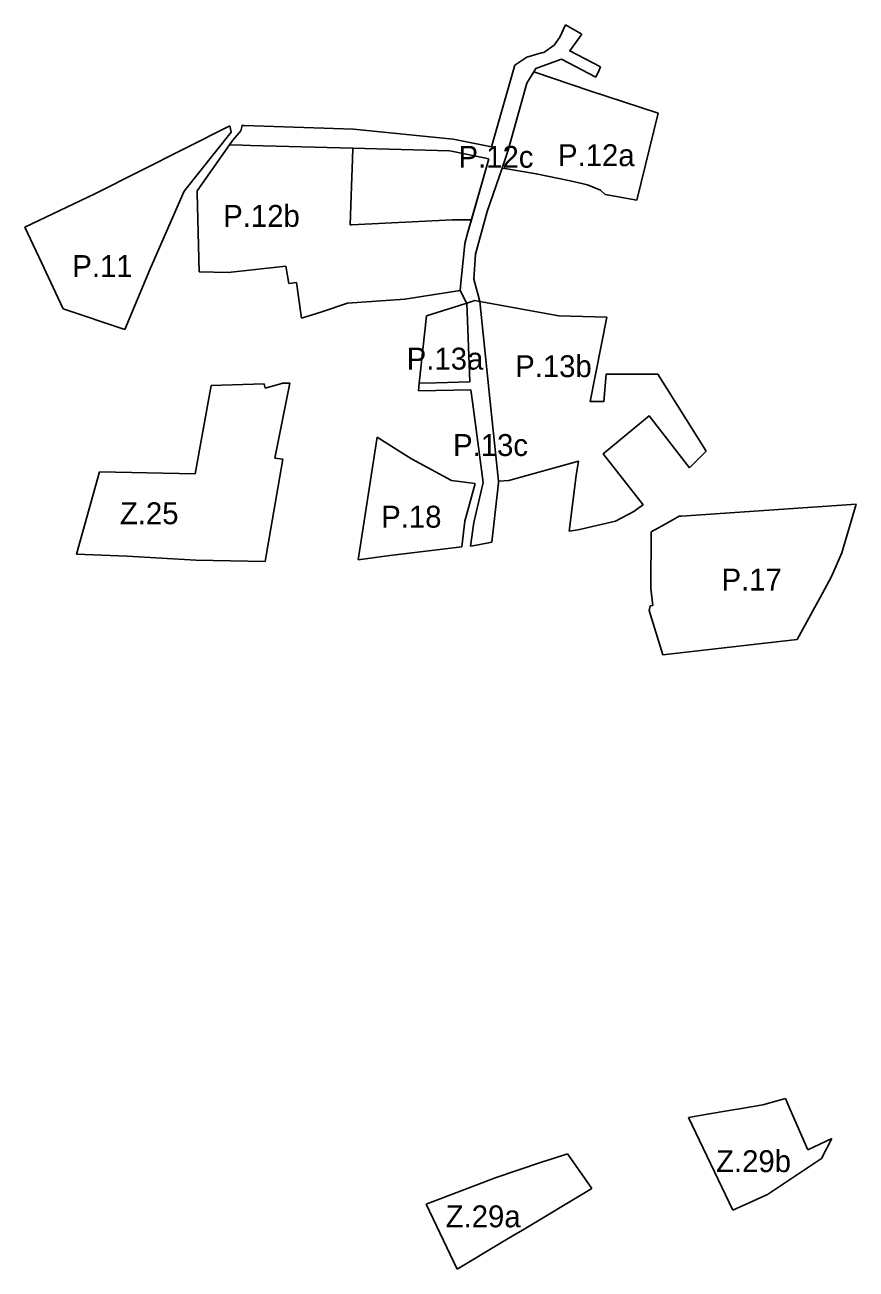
# Model space of a CAD drawing. Extents: x -438701 to -435614, y -1126017 to -1121766.
# Drawn here: x -438657 to -438278, y -1124714 to -1124146 of the extents above; entities that cross this region are included whole.
import ezdxf

# ---------------------------------------------------------------- set-up
doc = ezdxf.new("R2010")
doc.units = 0
for name, color, linetype in [('NAVRH', 7, 'Continuous'), ('STAV', 7, 'Continuous'), ('Vrstva 3', 7, 'Continuous'), ('Vrstva 6', 7, 'Continuous'), ('Vrstva 7', 7, 'Continuous'), ('Vrstva 9', 7, 'Continuous')]:
    doc.layers.add(name, color=color, linetype=linetype)

msp = doc.modelspace()

# ---------------------------------------------------------------- linework, layer by layer
at = {"layer": 'NAVRH'}
for p, q in [((-438572.39, -1124310.34), (-438579.69, -1124350.66)), ((-438548.15, -1124309.59), (-438572.39, -1124310.34)), ((-438547.64, -1124311.5), (-438548.15, -1124309.59)), ((-438540.13, -1124309.49), (-438547.64, -1124311.5)), ((-438543.36, -1124343.46), (-438536.39, -1124309.23)), ((-438536.39, -1124309.23), (-438540.17, -1124309.35)), ((-438540.17, -1124309.35), (-438540.13, -1124309.49)), ((-438579.69, -1124350.66), (-438623.38, -1124349.81)), ((-438610.69, -1124388.29), (-438579.35, -1124390.02)), ((-438579.35, -1124390.02), (-438547.72, -1124390.62)), ((-438547.72, -1124390.62), (-438547.25, -1124387.88)), ((-438310.12, -1124635.86), (-438320.49, -1124638.7)), ((-438309.13, -1124638.43), (-438310.12, -1124635.86)), ((-438299.98, -1124659.22), (-438309.13, -1124638.43)), ((-438346.75, -1124643.14), (-438354.53, -1124644.46)), ((-438354.53, -1124644.46), (-438334.17, -1124686.69)), ((-438289.07, -1124654.07), (-438299.98, -1124659.22)), ((-438293.79, -1124663.17), (-438289.07, -1124654.07)), ((-438318.45, -1124679.6), (-438293.79, -1124663.17)), ((-438421.5, -1124664.88), (-438442.23, -1124671.92)), ((-438442.23, -1124671.92), (-438474.16, -1124684.08)), ((-438398.6, -1124676.83), (-438398.85, -1124676.47)), ((-438334.17, -1124686.69), (-438318.45, -1124679.6)), ((-438474.16, -1124684.08), (-438460.03, -1124713.66))]:
    msp.add_line(p, q, dxfattribs=at)
for points in [[(-438547.25, -1124387.88), (-438539.7, -1124343.99), (-438543.36, -1124343.46)], [(-438623.38, -1124349.81), (-438633.77, -1124387.29), (-438610.69, -1124388.29)], [(-438320.49, -1124638.7), (-438330.3, -1124640.36), (-438334.93, -1124641.14), (-438346.75, -1124643.14)], [(-438409.64, -1124661.08), (-438416.72, -1124663.25), (-438421.5, -1124664.88)], [(-438398.85, -1124676.47), (-438408.93, -1124662.09), (-438409.64, -1124661.08)], [(-438460.03, -1124713.66), (-438438.34, -1124700.66), (-438433.47, -1124697.74), (-438431.04, -1124696.28), (-438398.6, -1124676.83)]]:
    msp.add_lwpolyline(points, dxfattribs=at)
at = {"layer": 'Vrstva 3'}
for p, q in [((-438410.68, -1124145.76), (-438413.25, -1124151.3)), ((-438403.24, -1124150), (-438410.68, -1124145.76)), ((-438407.85, -1124156.48), (-438403.24, -1124150)), ((-438416.19, -1124162.82), (-438412.51, -1124161.48)), ((-438412.51, -1124161.48), (-438396.78, -1124169.65)), ((-438433.82, -1124164.13), (-438444.44, -1124201.43)), ((-438425.04, -1124167.12), (-438428.21, -1124172.3)), ((-438428.21, -1124172.3), (-438425.04, -1124167.12)), ((-438399.58, -1124175.81), (-438425.04, -1124167.12)), ((-438428.21, -1124172.3), (-438436.78, -1124203)), ((-438436.78, -1124203), (-438428.21, -1124172.3)), ((-438368.37, -1124186.12), (-438399.58, -1124175.81)), ((-438378.08, -1124225.73), (-438368.37, -1124186.12)), ((-438563.77, -1124191.78), (-438625.53, -1124222.8)), ((-438563.18, -1124194.73), (-438563.77, -1124191.78)), ((-438584.64, -1124221.61), (-438563.18, -1124194.73)), ((-438558.89, -1124194.14), (-438562.44, -1124198.37)), ((-438461.91, -1124197.85), (-438507.43, -1124193.38)), ((-438563.95, -1124200.51), (-438578.71, -1124221.44)), ((-438562.44, -1124198.37), (-438563.95, -1124200.51)), ((-438558.18, -1124200.66), (-438563.95, -1124200.51)), ((-438563.95, -1124200.51), (-438558.18, -1124200.66)), ((-438554.42, -1124200.77), (-438558.18, -1124200.66)), ((-438558.18, -1124200.66), (-438554.42, -1124200.77)), ((-438507.72, -1124202.05), (-438554.42, -1124200.77)), ((-438554.42, -1124200.77), (-438507.72, -1124202.05)), ((-438507.88, -1124207.04), (-438507.72, -1124202.05)), ((-438507.72, -1124202.05), (-438463.62, -1124203.26)), ((-438463.62, -1124203.26), (-438461.94, -1124203.6)), ((-438444.44, -1124201.43), (-438461.91, -1124197.85)), ((-438436.78, -1124203), (-438439.6, -1124211.18)), ((-438439.6, -1124211.18), (-438436.78, -1124203)), ((-438508.29, -1124219.38), (-438507.88, -1124207.04)), ((-438461.94, -1124203.6), (-438445.6, -1124206.87)), ((-438445.6, -1124206.87), (-438455.16, -1124240.33)), ((-438446.4, -1124230.87), (-438439.6, -1124211.18)), ((-438508.87, -1124237.03), (-438508.29, -1124219.38)), ((-438625.53, -1124222.8), (-438657.4, -1124238.13)), ((-438600.25, -1124257.14), (-438584.64, -1124221.61)), ((-438578.71, -1124221.44), (-438578.71, -1124222.39)), ((-438578.71, -1124222.39), (-438577.81, -1124258.4)), ((-438392.51, -1124223.25), (-438378.08, -1124225.73)), ((-438451.69, -1124250.43), (-438446.4, -1124230.87)), ((-438453.54, -1124234.67), (-438462.13, -1124234.67)), ((-438455.16, -1124240.33), (-438453.54, -1124234.67)), ((-438657.4, -1124238.13), (-438649.87, -1124254.19)), ((-438456.63, -1124245.47), (-438455.16, -1124240.33)), ((-438455.16, -1124240.33), (-438456.63, -1124245.47)), ((-438458.38, -1124263.51), (-438456.95, -1124248.74)), ((-438456.95, -1124248.74), (-438458.38, -1124263.51)), ((-438456.95, -1124248.74), (-438456.63, -1124245.47)), ((-438456.63, -1124245.47), (-438456.95, -1124248.74)), ((-438452.46, -1124261.79), (-438451.69, -1124250.43)), ((-438611.81, -1124284.81), (-438600.25, -1124257.14)), ((-438577.81, -1124258.4), (-438564.55, -1124258.84)), ((-438564.55, -1124258.84), (-438553.52, -1124257.58)), ((-438553.52, -1124257.58), (-438538.33, -1124255.84)), ((-438538.33, -1124255.84), (-438536.95, -1124263.85)), ((-438536.95, -1124263.85), (-438533.42, -1124263.35)), ((-438533.42, -1124263.35), (-438531.11, -1124279.55)), ((-438458.72, -1124266.98), (-438458.38, -1124263.51)), ((-438458.38, -1124263.51), (-438458.72, -1124266.98)), ((-438451.33, -1124265.82), (-438452.46, -1124261.79)), ((-438450.59, -1124268.57), (-438451.33, -1124265.82)), ((-438458.72, -1124266.98), (-438456.07, -1124272.01)), ((-438455.7, -1124272.72), (-438451.99, -1124271.53)), ((-438451.99, -1124271.53), (-438455.7, -1124272.72)), ((-438451.99, -1124271.53), (-438449.67, -1124271.95)), ((-438449.67, -1124271.95), (-438451.99, -1124271.53)), ((-438449.67, -1124271.95), (-438450.59, -1124268.57)), ((-438639.93, -1124275.4), (-438611.81, -1124284.81)), ((-438461.91, -1124274.71), (-438474.13, -1124278.62)), ((-438455.7, -1124272.72), (-438461.91, -1124274.71)), ((-438456.07, -1124272.01), (-438455.93, -1124272.29)), ((-438455.93, -1124272.29), (-438455.7, -1124272.72)), ((-438454.27, -1124308.74), (-438455.7, -1124272.72)), ((-438455.7, -1124272.72), (-438454.27, -1124308.74)), ((-438449.67, -1124271.95), (-438444.96, -1124317.8)), ((-438444.96, -1124317.8), (-438449.67, -1124271.95)), ((-438474.13, -1124278.62), (-438477.39, -1124309.23)), ((-438346.45, -1124340.28), (-438368.49, -1124305.17)), ((-438477.39, -1124309.23), (-438477.78, -1124312.76)), ((-438477.39, -1124309.23), (-438469.62, -1124309.07)), ((-438469.62, -1124309.07), (-438477.39, -1124309.23)), ((-438469.62, -1124309.07), (-438454.27, -1124308.74)), ((-438454.27, -1124308.74), (-438469.62, -1124309.07)), ((-438477.78, -1124312.76), (-438453.79, -1124312.36)), ((-438453.79, -1124312.36), (-438453.06, -1124317.81)), ((-438453.06, -1124317.81), (-438448.16, -1124354.7)), ((-438444.96, -1124317.8), (-438441.24, -1124354.09)), ((-438441.24, -1124354.09), (-438444.96, -1124317.8)), ((-438444.96, -1124317.8), (-438444.96, -1124317.8)), ((-438444.96, -1124317.8), (-438444.96, -1124317.8)), ((-438496.56, -1124333.94), (-438505.21, -1124389.9)), ((-438486.97, -1124340.05), (-438496.56, -1124333.94)), ((-438480.86, -1124343.8), (-438486.97, -1124340.05)), ((-438462.72, -1124353.76), (-438480.86, -1124343.8)), ((-438354.09, -1124347.9), (-438346.45, -1124340.28)), ((-438451.84, -1124355.13), (-438462.72, -1124353.76)), ((-438456.53, -1124372.33), (-438451.84, -1124355.13)), ((-438448.16, -1124354.7), (-438452.48, -1124372.83)), ((-438277.96, -1124364.45), (-438357.71, -1124369.98)), ((-438284.52, -1124386.69), (-438277.96, -1124364.45)), ((-438457.93, -1124384), (-438456.53, -1124372.33)), ((-438452.48, -1124372.83), (-438454.01, -1124383.75)), ((-438363.73, -1124372.82), (-438371.47, -1124377.17)), ((-438358.81, -1124370.06), (-438363.73, -1124372.82)), ((-438357.71, -1124369.98), (-438358.81, -1124370.06)), ((-438408.88, -1124376.91), (-438404.82, -1124376.23)), ((-438371.47, -1124377.17), (-438371.73, -1124403.04)), ((-438490.87, -1124387.9), (-438457.93, -1124384)), ((-438454.01, -1124383.75), (-438451.27, -1124383.23)), ((-438451.27, -1124383.23), (-438444.23, -1124381.88)), ((-438505.21, -1124389.9), (-438490.87, -1124387.9)), ((-438289.23, -1124397.56), (-438284.52, -1124386.69)), ((-438293.49, -1124405.39), (-438289.23, -1124397.56)), ((-438371.73, -1124403.04), (-438370.76, -1124410.77)), ((-438304.86, -1124426.28), (-438293.49, -1124405.39)), ((-438371.91, -1124410.92), (-438372.46, -1124413.12)), ((-438372.46, -1124413.12), (-438366.13, -1124433.36)), ((-438370.76, -1124410.77), (-438371.91, -1124410.92)), ((-438366.13, -1124433.36), (-438324.89, -1124428.6)), ((-438324.89, -1124428.6), (-438304.86, -1124426.28))]:
    msp.add_line(p, q, dxfattribs=at)
for points in [[(-438413.25, -1124151.3), (-438415.8, -1124155.01), (-438420.57, -1124158.3)], [(-438394.63, -1124164.9), (-438408.69, -1124157.66), (-438407.85, -1124156.48)], [(-438420.57, -1124158.3), (-438421.6, -1124158.59), (-438428.21, -1124160.42), (-438433.82, -1124164.13)], [(-438425.04, -1124167.12), (-438424.18, -1124165.72), (-438416.19, -1124162.82)], [(-438396.78, -1124169.65), (-438395.43, -1124166.67), (-438394.63, -1124164.9)], [(-438507.43, -1124193.38), (-438557.27, -1124191.7), (-438558.27, -1124191.67), (-438558.89, -1124194.14)], [(-438439.6, -1124211.18), (-438438.29, -1124211.37), (-438424, -1124213.73), (-438408.51, -1124217.01), (-438400.53, -1124218.7), (-438394.57, -1124221.19), (-438392.51, -1124223.25)], [(-438462.13, -1124234.67), (-438508.26, -1124237), (-438508.87, -1124237.03)], [(-438649.87, -1124254.19), (-438644.51, -1124265.63), (-438639.93, -1124275.4)], [(-438531.11, -1124279.55), (-438522.35, -1124276.86), (-438510.06, -1124272.84), (-438484.02, -1124270.93), (-438458.72, -1124266.98)], [(-438391.78, -1124279.14), (-438413.63, -1124278.54), (-438449.67, -1124271.95)], [(-438368.49, -1124305.17), (-438392.08, -1124305.24), (-438393.17, -1124317.69), (-438399.29, -1124317.72), (-438391.78, -1124279.14)], [(-438375.22, -1124364.76), (-438393.49, -1124341.6), (-438372.43, -1124324.16), (-438354.09, -1124347.9)], [(-438441.24, -1124354.09), (-438436.45, -1124353.73), (-438404.63, -1124344.93), (-438405.74, -1124351.49), (-438408.88, -1124376.91)], [(-438444.23, -1124381.88), (-438441.17, -1124354.72), (-438441.24, -1124354.09)], [(-438404.82, -1124376.23), (-438387.84, -1124372.24), (-438379.48, -1124367.79), (-438377.56, -1124366.43), (-438375.22, -1124364.76)]]:
    msp.add_lwpolyline(points, dxfattribs=at)
at = {"layer": 'Vrstva 6'}
for p, q in [((-438572.39, -1124310.34), (-438579.69, -1124350.66)), ((-438548.15, -1124309.59), (-438572.39, -1124310.34)), ((-438547.64, -1124311.5), (-438548.15, -1124309.59)), ((-438540.13, -1124309.49), (-438547.64, -1124311.5)), ((-438543.36, -1124343.46), (-438536.39, -1124309.23)), ((-438536.39, -1124309.23), (-438540.17, -1124309.35)), ((-438540.17, -1124309.35), (-438540.13, -1124309.49)), ((-438579.69, -1124350.66), (-438623.38, -1124349.81)), ((-438610.69, -1124388.29), (-438579.35, -1124390.02)), ((-438579.35, -1124390.02), (-438547.72, -1124390.62)), ((-438547.72, -1124390.62), (-438547.25, -1124387.88)), ((-438310.12, -1124635.86), (-438320.49, -1124638.7)), ((-438309.13, -1124638.43), (-438310.12, -1124635.86)), ((-438299.98, -1124659.22), (-438309.13, -1124638.43)), ((-438346.75, -1124643.14), (-438354.53, -1124644.46)), ((-438354.53, -1124644.46), (-438334.17, -1124686.69)), ((-438289.07, -1124654.07), (-438299.98, -1124659.22)), ((-438293.79, -1124663.17), (-438289.07, -1124654.07)), ((-438318.45, -1124679.6), (-438293.79, -1124663.17)), ((-438421.5, -1124664.88), (-438442.23, -1124671.92)), ((-438442.23, -1124671.92), (-438474.16, -1124684.08)), ((-438398.6, -1124676.83), (-438398.85, -1124676.47)), ((-438334.17, -1124686.69), (-438318.45, -1124679.6)), ((-438474.16, -1124684.08), (-438460.03, -1124713.66))]:
    msp.add_line(p, q, dxfattribs=at)
for points in [[(-438547.25, -1124387.88), (-438539.7, -1124343.99), (-438543.36, -1124343.46)], [(-438623.38, -1124349.81), (-438633.77, -1124387.29), (-438610.69, -1124388.29)], [(-438320.49, -1124638.7), (-438330.3, -1124640.36), (-438334.93, -1124641.14), (-438346.75, -1124643.14)], [(-438409.64, -1124661.08), (-438416.72, -1124663.25), (-438421.5, -1124664.88)], [(-438398.85, -1124676.47), (-438408.93, -1124662.09), (-438409.64, -1124661.08)], [(-438460.03, -1124713.66), (-438438.34, -1124700.66), (-438433.47, -1124697.74), (-438431.04, -1124696.28), (-438398.6, -1124676.83)]]:
    msp.add_lwpolyline(points, dxfattribs=at)
at = {"layer": 'Vrstva 7'}
for p, q in [((-438410.68, -1124145.76), (-438413.25, -1124151.3)), ((-438403.24, -1124150), (-438410.68, -1124145.76)), ((-438407.85, -1124156.48), (-438403.24, -1124150)), ((-438416.19, -1124162.82), (-438412.51, -1124161.48)), ((-438412.51, -1124161.48), (-438396.78, -1124169.65)), ((-438433.82, -1124164.13), (-438444.44, -1124201.43)), ((-438425.04, -1124167.12), (-438428.21, -1124172.3)), ((-438428.21, -1124172.3), (-438425.04, -1124167.12)), ((-438399.58, -1124175.81), (-438425.04, -1124167.12)), ((-438428.21, -1124172.3), (-438436.78, -1124203)), ((-438436.78, -1124203), (-438428.21, -1124172.3)), ((-438368.37, -1124186.12), (-438399.58, -1124175.81)), ((-438378.08, -1124225.73), (-438368.37, -1124186.12)), ((-438563.77, -1124191.78), (-438625.53, -1124222.8)), ((-438563.18, -1124194.73), (-438563.77, -1124191.78)), ((-438584.64, -1124221.61), (-438563.18, -1124194.73)), ((-438558.89, -1124194.14), (-438562.44, -1124198.37)), ((-438461.91, -1124197.85), (-438507.43, -1124193.38)), ((-438563.95, -1124200.51), (-438578.71, -1124221.44)), ((-438562.44, -1124198.37), (-438563.95, -1124200.51)), ((-438558.18, -1124200.66), (-438563.95, -1124200.51)), ((-438563.95, -1124200.51), (-438558.18, -1124200.66)), ((-438554.42, -1124200.77), (-438558.18, -1124200.66)), ((-438558.18, -1124200.66), (-438554.42, -1124200.77)), ((-438507.72, -1124202.05), (-438554.42, -1124200.77)), ((-438554.42, -1124200.77), (-438507.72, -1124202.05)), ((-438507.88, -1124207.04), (-438507.72, -1124202.05)), ((-438507.72, -1124202.05), (-438463.62, -1124203.26)), ((-438463.62, -1124203.26), (-438461.94, -1124203.6)), ((-438444.44, -1124201.43), (-438461.91, -1124197.85)), ((-438436.78, -1124203), (-438439.6, -1124211.18)), ((-438439.6, -1124211.18), (-438436.78, -1124203)), ((-438508.29, -1124219.38), (-438507.88, -1124207.04)), ((-438461.94, -1124203.6), (-438445.6, -1124206.87)), ((-438445.6, -1124206.87), (-438453.54, -1124234.67)), ((-438446.4, -1124230.87), (-438439.6, -1124211.18)), ((-438508.87, -1124237.03), (-438508.29, -1124219.38)), ((-438625.53, -1124222.8), (-438657.4, -1124238.13)), ((-438600.25, -1124257.14), (-438584.64, -1124221.61)), ((-438578.71, -1124221.44), (-438578.71, -1124222.39)), ((-438578.71, -1124222.39), (-438577.81, -1124258.4)), ((-438392.51, -1124223.25), (-438378.08, -1124225.73)), ((-438451.69, -1124250.43), (-438446.4, -1124230.87)), ((-438453.54, -1124234.67), (-438462.13, -1124234.67)), ((-438455.16, -1124240.33), (-438453.54, -1124234.67)), ((-438453.54, -1124234.67), (-438455.16, -1124240.33)), ((-438657.4, -1124238.13), (-438649.87, -1124254.19)), ((-438456.63, -1124245.47), (-438455.16, -1124240.33)), ((-438455.16, -1124240.33), (-438456.63, -1124245.47)), ((-438458.38, -1124263.51), (-438456.95, -1124248.74)), ((-438456.95, -1124248.74), (-438458.38, -1124263.51)), ((-438456.95, -1124248.74), (-438456.63, -1124245.47)), ((-438456.63, -1124245.47), (-438456.95, -1124248.74)), ((-438452.46, -1124261.79), (-438451.69, -1124250.43)), ((-438611.81, -1124284.81), (-438600.25, -1124257.14)), ((-438577.81, -1124258.4), (-438564.55, -1124258.84)), ((-438564.55, -1124258.84), (-438553.52, -1124257.58)), ((-438553.52, -1124257.58), (-438538.33, -1124255.84)), ((-438538.33, -1124255.84), (-438536.95, -1124263.85)), ((-438536.95, -1124263.85), (-438533.42, -1124263.35)), ((-438533.42, -1124263.35), (-438531.11, -1124279.55)), ((-438458.72, -1124266.98), (-438458.38, -1124263.51)), ((-438458.38, -1124263.51), (-438458.72, -1124266.98)), ((-438451.33, -1124265.82), (-438452.46, -1124261.79)), ((-438450.59, -1124268.57), (-438451.33, -1124265.82)), ((-438458.72, -1124266.98), (-438456.07, -1124272.01)), ((-438455.7, -1124272.72), (-438451.99, -1124271.53)), ((-438451.99, -1124271.53), (-438455.7, -1124272.72)), ((-438451.99, -1124271.53), (-438449.67, -1124271.95)), ((-438449.67, -1124271.95), (-438451.99, -1124271.53)), ((-438449.67, -1124271.95), (-438450.59, -1124268.57)), ((-438639.93, -1124275.4), (-438611.81, -1124284.81)), ((-438461.91, -1124274.71), (-438474.13, -1124278.62)), ((-438455.7, -1124272.72), (-438461.91, -1124274.71)), ((-438456.07, -1124272.01), (-438455.93, -1124272.29)), ((-438455.93, -1124272.29), (-438455.7, -1124272.72)), ((-438455.7, -1124272.72), (-438454.27, -1124308.74)), ((-438454.27, -1124308.74), (-438455.7, -1124272.72)), ((-438449.67, -1124271.95), (-438444.96, -1124317.8)), ((-438444.96, -1124317.8), (-438449.67, -1124271.95)), ((-438474.13, -1124278.62), (-438477.39, -1124309.23)), ((-438346.45, -1124340.28), (-438368.49, -1124305.17)), ((-438477.39, -1124309.23), (-438477.78, -1124312.76)), ((-438469.62, -1124309.07), (-438477.39, -1124309.23)), ((-438477.39, -1124309.23), (-438469.62, -1124309.07)), ((-438454.27, -1124308.74), (-438469.62, -1124309.07)), ((-438469.62, -1124309.07), (-438454.27, -1124308.74)), ((-438477.78, -1124312.76), (-438453.79, -1124312.36)), ((-438453.79, -1124312.36), (-438453.06, -1124317.81)), ((-438453.06, -1124317.81), (-438448.16, -1124354.7)), ((-438444.96, -1124317.8), (-438441.24, -1124354.09)), ((-438441.24, -1124354.09), (-438444.96, -1124317.8)), ((-438496.56, -1124333.94), (-438505.21, -1124389.9)), ((-438486.97, -1124340.05), (-438496.56, -1124333.94)), ((-438480.86, -1124343.8), (-438486.97, -1124340.05)), ((-438462.72, -1124353.76), (-438480.86, -1124343.8)), ((-438354.09, -1124347.9), (-438346.45, -1124340.28)), ((-438451.84, -1124355.13), (-438462.72, -1124353.76)), ((-438456.53, -1124372.33), (-438451.84, -1124355.13)), ((-438448.16, -1124354.7), (-438452.48, -1124372.83)), ((-438277.96, -1124364.45), (-438357.71, -1124369.98)), ((-438284.52, -1124386.69), (-438277.96, -1124364.45)), ((-438457.93, -1124384), (-438456.53, -1124372.33)), ((-438452.48, -1124372.83), (-438454.01, -1124383.75)), ((-438363.73, -1124372.82), (-438371.47, -1124377.17)), ((-438358.81, -1124370.06), (-438363.73, -1124372.82)), ((-438357.71, -1124369.98), (-438358.81, -1124370.06)), ((-438408.88, -1124376.91), (-438404.82, -1124376.23)), ((-438371.47, -1124377.17), (-438371.73, -1124403.04)), ((-438490.87, -1124387.9), (-438457.93, -1124384)), ((-438454.01, -1124383.75), (-438451.27, -1124383.23)), ((-438451.27, -1124383.23), (-438444.23, -1124381.88)), ((-438505.21, -1124389.9), (-438490.87, -1124387.9)), ((-438289.23, -1124397.56), (-438284.52, -1124386.69)), ((-438293.49, -1124405.39), (-438289.23, -1124397.56)), ((-438371.73, -1124403.04), (-438370.76, -1124410.77)), ((-438304.86, -1124426.28), (-438293.49, -1124405.39)), ((-438371.91, -1124410.92), (-438372.46, -1124413.12)), ((-438372.46, -1124413.12), (-438366.13, -1124433.36)), ((-438370.76, -1124410.77), (-438371.91, -1124410.92)), ((-438366.13, -1124433.36), (-438324.89, -1124428.6)), ((-438324.89, -1124428.6), (-438304.86, -1124426.28))]:
    msp.add_line(p, q, dxfattribs=at)
for points in [[(-438413.25, -1124151.3), (-438415.8, -1124155.01), (-438420.57, -1124158.3)], [(-438394.63, -1124164.9), (-438408.69, -1124157.66), (-438407.85, -1124156.48)], [(-438420.57, -1124158.3), (-438421.6, -1124158.59), (-438428.21, -1124160.42), (-438433.82, -1124164.13)], [(-438425.04, -1124167.12), (-438424.18, -1124165.72), (-438416.19, -1124162.82)], [(-438396.78, -1124169.65), (-438395.43, -1124166.67), (-438394.63, -1124164.9)], [(-438507.43, -1124193.38), (-438557.27, -1124191.7), (-438558.27, -1124191.67), (-438558.89, -1124194.14)], [(-438439.6, -1124211.18), (-438438.29, -1124211.37), (-438424, -1124213.73), (-438408.51, -1124217.01), (-438400.53, -1124218.7), (-438394.57, -1124221.19), (-438392.51, -1124223.25)], [(-438462.13, -1124234.67), (-438508.26, -1124237), (-438508.87, -1124237.03)], [(-438649.87, -1124254.19), (-438644.51, -1124265.63), (-438639.93, -1124275.4)], [(-438531.11, -1124279.55), (-438522.35, -1124276.86), (-438510.06, -1124272.84), (-438484.02, -1124270.93), (-438458.72, -1124266.98)], [(-438391.78, -1124279.14), (-438413.63, -1124278.54), (-438449.67, -1124271.95)], [(-438368.49, -1124305.17), (-438392.08, -1124305.24), (-438393.17, -1124317.69), (-438399.29, -1124317.72), (-438391.78, -1124279.14)], [(-438375.22, -1124364.76), (-438393.49, -1124341.6), (-438372.43, -1124324.16), (-438354.09, -1124347.9)], [(-438441.24, -1124354.09), (-438436.45, -1124353.73), (-438404.63, -1124344.93), (-438405.74, -1124351.49), (-438408.88, -1124376.91)], [(-438444.23, -1124381.88), (-438441.17, -1124354.72), (-438441.24, -1124354.09)], [(-438404.82, -1124376.23), (-438387.84, -1124372.24), (-438379.48, -1124367.79), (-438377.56, -1124366.43), (-438375.22, -1124364.76)]]:
    msp.add_lwpolyline(points, dxfattribs=at)

# ---------------------------------------------------------------- texts
at = {"layer": 'STAV'}
for s, p in [('P.12c', (-438459.45, -1124210.97)), ('P.12a', (-438414.03, -1124210.23)), ('P.12b', (-438566.85, -1124237.95)), ('P.11', (-438635.75, -1124260.85)), ('P.13a', (-438483.08, -1124303.09)), ('P.13b', (-438433.58, -1124306.54)), ('P.13c', (-438461.93, -1124342.54)), ('P.18', (-438494.74, -1124375.24)), ('P.17', (-438339.37, -1124403.93))]:
    msp.add_text(s, height=10, dxfattribs=at).set_placement(p)
at = {"layer": 'Vrstva 9'}
for s, p in [('Z.25', (-438614.03, -1124373.67)), ('Z.29b', (-438341.88, -1124669.4)), ('Z.29a', (-438465.31, -1124694.58))]:
    msp.add_text(s, height=10, dxfattribs=at).set_placement(p)

doc.saveas('drawing.dxf')
